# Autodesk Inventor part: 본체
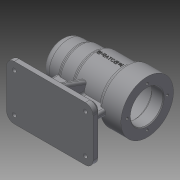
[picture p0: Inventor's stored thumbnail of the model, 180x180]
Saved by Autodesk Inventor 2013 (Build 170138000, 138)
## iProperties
Created: 2016-06
Part Number: 본체
Material: 일반
Document SubType Name: Modeling
Designer: Administrator
Density: 1 g/cm^3
Author: Administrator
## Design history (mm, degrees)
sketch "스케치1"
  geometry: L1 (-56, 34)-(28, 34); L2 (56, 34)-(56, 0); L3 (56, 0)-(-56, 0); L4 (-56, 0)-(-56, 25); L5 (28, 34)-(28, 30); L6 (28, 30)-(-11, 30); L7 (-11, 30)-(-11, 27); L8 (-11, 27)-(-31, 27); L9 (-31, 27)-(-31, 25); L10 (-31, 25)-(-56, 25); L11 (28, 34)-(56, 34); L12 (-56, 25)-(-56, 34); L13 (-56, -60)-(56, -60); L14 (56, -60)-(56, -70); L15 (56, -70)-(-56, -70); L16 (-56, -70)-(-56, -60); L17 (-36, 0)-(36, 0); L18 (36, 0)-(36, -60); L19 (36, -60)-(-36, -60); L20 (-36, -60)-(-36, 0); 3 further points
  constraints: 40 end point, 13 parallel, 5 perpendicular, 4 horizontal, 2 midpoint, 2 point on line, 1 coincident, 1 vertical alignment
  dimensions: "d0" = 112 distance of L1.start L2.start; "d2" = 68 diameter of L1 L3; "d3" = 84 distance between parallel lines of L5 L4; "d4" = 45 distance between parallel lines of L7 L4; "d5" = 25 distance between parallel lines of L9 L4; "d6" = 60 diameter of L6 L3; "d7" = 54 diameter of L8 L3; "d8" = 50 diameter of L10 L3; "d9" = 10 distance between parallel lines of L15 L13; "d11" = 70 distance from line of L15 point (0, 0); "d12" = 20 distance from line of L19.end L16; "d13" = 20 distance between parallel lines of L18 L14; "d15" = 72 distance between parallel lines of L18 L20
revolve "회전1" stored, may be unused: angle "d16" = 90 deg
extrude "돌출1" join sketch "스케치1" stored distance "d17" = 70; taper "d18" = 0 deg
extrude "돌출2" join sketch "스케치1" stored distance "d19" = 8; taper "d20" = 0 deg
sketch "스케치2"
  geometry: L1 (-60, -35)-(-70, -35) reference; L2 (-70, -35)-(-70, 35) reference; L3 (-70, 35)-(-60, 35) reference; L4 (-60, 35)-(-60, 4) reference; L5 (-60, 4)-(-29.732, 4) reference; L6 (-29.732, -4)-(-60, -4) reference; L7 (-60, -4)-(-60, -35) reference; L8 (-60, 28)-(0, 6.162); L9 (0, 6.162)-(0, -6.162); L10 (0, -6.162)-(-60, -28); L11 (-60, -28)-(-60, 28); A1 r 30 centre (0, 0) between (-29.732, -4) and (-29.732, 4) reference; 1 further point
  constraints: 8 end point, 2 parallel, 2 point on line
  dimensions: "d21" = 7 distance from line of L8.start L3; "d22" = 7 distance from line of L10.end L1; "d23" = 110 deg angle of L4 L8; "d24" = 110 deg angle of L7 L10; "d25" = 60 distance from line of L7 L9.end
extrude "돌출3" join sketch "스케치2" stored distance "d26" = 8; taper "d27" = 0 deg
sketch "스케치3"
  geometry: 2 further points
  dimensions: "d28" = 25 vertical distance of point (56, 35) point (10, 60); "d29" = 46 horizontal distance of point (56, 35) point (10, 60)
hole "구멍1" sketch "스케치3" at (10, 60) diameter "d30" = 5; stored, may be unused: countersink angle "d34" = 90 deg, drill point angle "d36" = 118 deg; dims "d31" = 6, "d32" = 9, "d33" = 4, "d35" = 8
sketch "스케치4"
  geometry: L1 (-56, -25)-(-56, 25) reference; L2 (-56, 25)-(-31, 25) reference; L3 (-31, 25)-(-31, 27) reference; L4 (-31, 27)-(-11, 27) reference; L5 (-11, 27)-(-11, 30) reference; L6 (-11, 30)-(28, 30) reference; L7 (28, 30)-(28, 34) reference; L8 (28, 34)-(56, 34) reference; L9 (56, 34)-(56, -34) reference; L10 (56, -34)-(36, -34) reference; L11 (36, -34)-(36, -60) reference; L12 (36, -60)-(56, -60) reference; L13 (56, -60)-(56, -70) reference; L14 (56, -70)-(-56, -70) reference; L15 (-56, -70)-(-56, -60) reference; L16 (-56, -60)-(-36, -60) reference; L17 (-36, -60)-(-36, -25) reference; L18 (-36, -25)-(-56, -25) reference; L19 (56, 0)-(-50, 0); L20 (56, 21)-(56, 0); L21 (56, 21)-(41, 21); L22 (41, 21)-(41, 24); L23 (41, 24)-(-13, 24); L24 (-13, 24)-(-13, 21); L25 (-13, 21)-(-25, 21); L26 (-25, 21)-(-25, 17.5); L27 (-25, 17.5)-(-43, 17.5); L28 (-43, 17.5)-(-43, 16); L29 (-43, 16)-(-47, 16); L30 (-47, 16)-(-47, 10.5); L31 (-47, 10.5)-(-50, 10.5); L32 (-50, 10.5)-(-50, 0); 1 further point
  constraints: 28 end point, 6 parallel, 6 perpendicular, 2 collinear, 1 midpoint, 1 point on line
  dimensions: "d45" = 15 distance of L20.start L21.end; "d47" = 54 distance of L22.end L23.end; "d48" = 12 distance of L24.end L25.end; "d49" = 18 distance of L26.end L27.end; "d50" = 4 distance of L28.end L29.end; "d51" = 3 distance of L30.end L31.end; "d52" = 42 diameter of L21 L19; "d53" = 48 diameter of L23 L19; "d54" = 42 diameter of L25 L19; "d55" = 35 diameter of L27 L19; "d56" = 32 diameter of L29 L19; "d57" = 21 diameter of L31 L19
revolve "회전2" sketch "스케치4" stored, may be unused: angle "d58" = 90 deg
fillet "모깎기1" dims "d59" = 10
sketch "스케치5"
  geometry: C1 r 21 at (0, 0) reference; 1 further point
  constraints: 1 vertical alignment
  dimensions: "d60" = 26 distance of C1.centre point (0, 26)
hole "구멍2" sketch "스케치5" at (0, 26) diameter "d61" = 3.242; stored, may be unused: countersink angle "d65" = 90 deg, drill point angle "d67" = 118 deg; dims "d62" = 8, "d63" = 9, "d64" = 4, "d66" = 11
node "작업 평면1"
sketch "스케치6"
  geometry: L1 (47.5, -34)-(47.5, 34) reference; L2 (-4.5, -25.68)-(-4.5, -29.732) reference; L3 (-4.5, -29.732)-(19.5, -29.732) reference; L4 (19.5, -29.732)-(19.5, -29.732) reference; L5 (19.5, -29.732)-(-4.5, -29.732) reference; L6 (-4.5, -29.732)-(-4.5, -25.68) reference; L7 (-4.5, -25.68)-(-12.5, -25.68) reference; L8 (-12.5, -25.68)-(-12.5, -29.732) reference; L9 (-12.5, -29.732)-(-19.5, -29.732) reference; L10 (-19.5, -29.732)-(-19.5, -29.732) reference; L11 (-19.5, -29.732)-(-12.5, -29.732) reference; L12 (-12.5, -29.732)-(-12.5, -25.68) reference; L13 (-12.5, -25.68)-(-4.5, -25.68) reference; 2 further points
  constraints: 1 horizontal alignment, 1 other
  dimensions: "d71" = 48 distance from line of L1 point (-0.5, 0)
feature "엠보싱1" sketch "스케치6" dims "d0" = 112, "d2" = 68, "d3" = 84, "d4" = 45, "d5" = 25, "d6" = 60, "d7" = 54, "d8" = 50, "d9" = 10, "d11" = 70, "d12" = 20, "d13" = 20, "d15" = 72, "d72" = 0.5, "d73" = 0
fillet "모깎기2" dims "d74" = 10
fillet "모깎기3" dims "d75" = 3
fillet "모깎기4" dims "d76" = 0.3
fillet "모깎기5" dims "d77" = 3
chamfer "모따기1" distance "d78" = 4; stored, may be unused: second distance "d79" = 2, angle "d80" = 45 deg
fillet "모깎기6" dims "d81" = 3
fillet "모깎기7" dims "d82" = 3
fillet "모깎기8" dims "d83" = 3
fillet "모깎기9" dims "d84" = 3
fillet "모깎기10" dims "d85" = 3
chamfer "모따기2" distance "d86" = 1; stored, may be unused: second distance "d87" = 2, angle "d88" = 45 deg
node "솔리드1"
pattern_linear "직사각형 패턴1" dims "d39" = 92
pattern_circular "원형 패턴1" dims angle "d69" = 360 deg
node "투영된 루프1"
node "절단 모서리 투영1"
node "절단 모서리 투영2"
